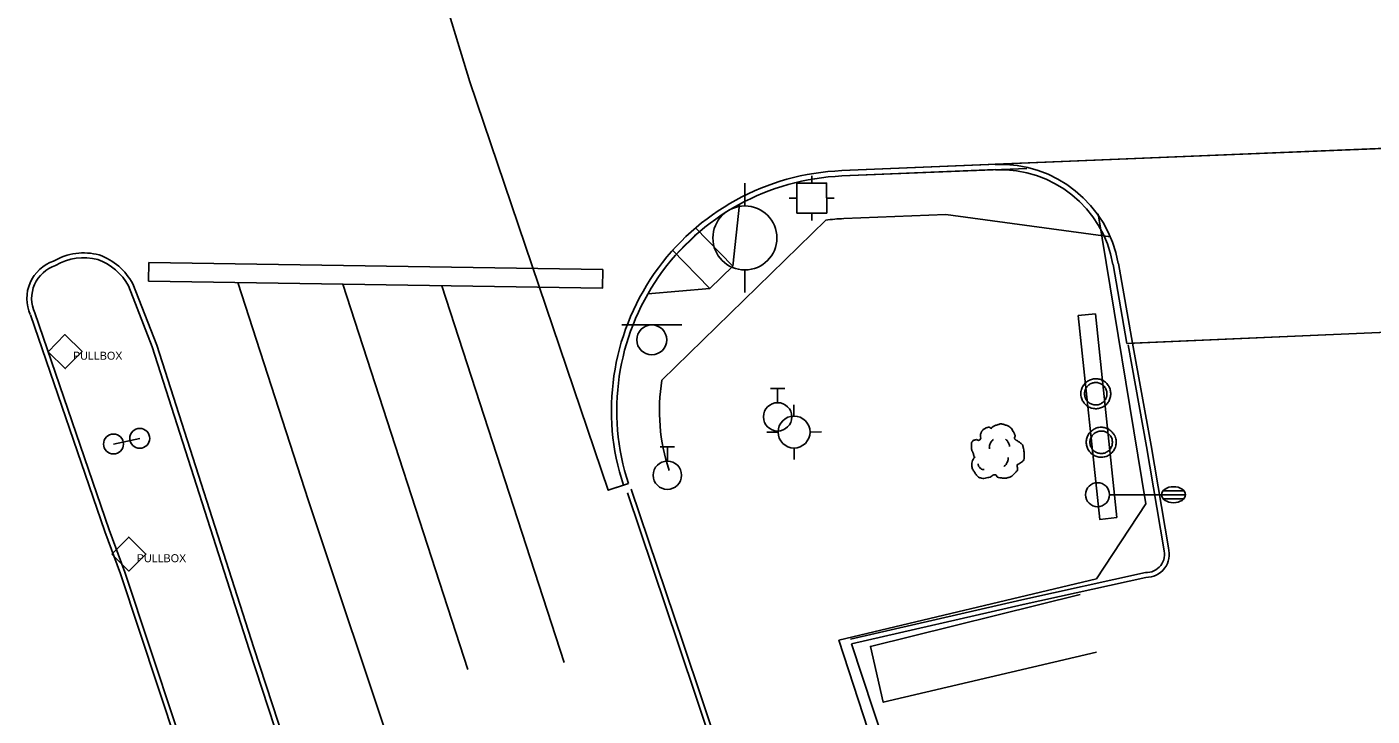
# Model space of a CAD drawing. Extents: x 2145380 to 2157287, y 139568 to 149130.
# Drawn here: x 2147393.3 to 2147561.3, y 142844.8 to 142930.9 of the extents above; entities that cross this region are included whole.
import ezdxf

# ---------------------------------------------------------------- set-up
doc = ezdxf.new("R2010")
doc.units = 0
for name, color, linetype in [('Default', 7, 'Continuous'), ('PR_PREVIOUSLY CONSTRUCTED', 7, 'Continuous'), ('TOPO_Asphalt', 7, 'Continuous'), ('TOPO_Concrete', 7, 'Continuous'), ('TOPO_Curb Back', 7, 'Continuous'), ('TOPO_Guardrail', 7, 'Continuous'), ('TOPO_Light Pole', 7, 'Continuous'), ('TOPO_Misc', 7, 'Continuous'), ('TOPO_Misc Line', 7, 'Continuous'), ('TOPO_Power Pole', 7, 'Continuous'), ('TOPO_Power Pullbox', 7, 'Continuous'), ('TOPO_Sign', 7, 'Continuous'), ('TOPO_Traffic Signal', 7, 'Continuous'), ('TOPO_Tree', 7, 'Continuous'), ('TOPO_Wall Freestanding', 7, 'Continuous'), ('TOPO_Water Fire Hydrant', 7, 'Continuous'), ('TOPO_Water Valve', 7, 'Continuous')]:
    doc.layers.add(name, color=color, linetype=linetype)

# ---------------------------------------------------------------- blocks, each defined once
blk = doc.blocks.new('POST')
at = {"layer": 'TOPO_Misc'}
for start, end in [(90, 180), (180, 270), (360, 90), (270, 0)]:
    blk.add_arc((-0.01, 0.03), 3.16, start, end, dxfattribs=at)
blk = doc.blocks.new('FIRHYD')
at = {"layer": 'TOPO_Water Fire Hydrant'}
for p, q in [((-0.02, 10.16), (-0.03, 17.34)), ((10.16, 0.02), (17.34, 0.03)), ((-10.16, -0.02), (-17.34, -0.03)), ((0.02, -10.16), (0.03, -17.34))]:
    blk.add_line(p, q, dxfattribs=at)
blk.add_circle((0, 0), 10.16, dxfattribs=at)
blk = doc.blocks.new('LP')
at = {"layer": 'TOPO_Light Pole'}
blk.add_line((3.81, 0), (20.32, 0), dxfattribs=at)
for points in [[(20.32, 0), (27.94, 0)], [(20.32, 0), (23.5, 0)], [(20.83, 1.27), (27.43, 1.27)], [(20.83, 1.27), (23.5, 1.27)], [(23.71, 1.27), (27.43, 1.27)], [(23.71, 0), (27.94, 0)], [(20.83, -1.27), (27.43, -1.27)], [(20.83, -1.27), (23.5, -1.27)], [(23.71, -1.27), (27.43, -1.27)]]:
    blk.add_lwpolyline(points, dxfattribs=at)
blk.add_circle((0, 0), 3.81, dxfattribs=at)
blk.add_ellipse((24.13, 0), major_axis=(3.81, 0), ratio=0.666667, dxfattribs=at)
blk = doc.blocks.new('TRFSIG')
at = {"layer": 'TOPO_Traffic Signal'}
for p, q in [((0.04, 4.66), (0.04, 7.04)), ((-4.7, -0.09), (-7.08, -0.09)), ((4.79, -0.09), (7.17, -0.09)), ((0.04, -4.83), (0.04, -7.22))]:
    blk.add_line(p, q, dxfattribs=at)
blk.add_lwpolyline([(-4.7, -4.85), (4.81, -4.83), (4.79, 4.67), (-4.72, 4.66), (-4.7, -4.85)], dxfattribs=at)
blk = doc.blocks.new('TREE')
at = {"layer": 'TOPO_Tree'}
for points in [[(-14.07, -0.4), (-14.17, 0.5), (-14.37, 1.38), (-14.6, 2.25), (-14.84, 3.17), (-15.47, 3.96), (-15.66, 4.9), (-15.8, 5.59), (-15.71, 6.31), (-15.66, 7.01), (-15.6, 7.91), (-15.72, 8.8), (-15.13, 9.66), (-14.62, 10.42), (-13.76, 10.49), (-13.02, 10.72), (-12.18, 10.98), (-11.06, 10), (-10.37, 10.72), (-9.4, 11.74), (-10.29, 13.28), (-9.84, 14.42), (-9.56, 15.15), (-9.32, 15.89), (-8.78, 16.54), (-8.18, 17.26), (-7.5, 17.68), (-6.67, 18.13), (-6.14, 18.41), (-5.61, 18.61), (-5.08, 18.66), (-4.55, 18.71), (-4.02, 18.54), (-3.49, 18.13)], [(-3.49, 17.6), (-3.07, 18.27), (-2.58, 18.8), (-1.9, 19.19), (-1.05, 19.68), (-0.19, 19.96), (0.74, 20.24), (1.62, 20.51), (2.51, 20.82), (3.39, 20.77), (4.1, 20.73), (4.8, 20.47), (5.51, 20.24), (6.43, 19.95), (7.32, 19.73), (8.15, 19.19), (9.36, 18.4), (10.02, 17.21), (10.8, 16.01), (11.24, 15.33), (11.58, 14.62), (11.86, 13.89), (12.17, 13.08), (11.37, 12.02), (11.86, 11.25), (12, 11.03), (12.18, 10.86), (12.39, 10.72), (12.91, 10.35), (13.45, 10.02), (13.97, 9.66), (14.7, 9.16), (15.41, 8.68), (16.09, 8.07), (16.7, 7.53), (16.93, 6.73), (17.15, 5.95), (17.59, 4.38), (17.71, 2.77), (17.68, 1.19), (17.65, -0.25), (17.83, -2.22), (16.62, -3.04), (15.47, -3.83), (14.31, -4.58), (13.16, -5.35)], [(-4.21, 5.09), (-4.46, 6.09), (-4.3, 7.21), (-3.84, 8.21), (-3.33, 9.34), (-2.71, 10.27), (-1.64, 10.97)], [(5.89, 11.15), (6.5, 10.68), (6.96, 10.17), (7.36, 9.5), (7.93, 8.56), (8.31, 7.6), (8.46, 6.56)], [(13.16, -5.34), (13.25, -5.81), (13.36, -6.28), (13.45, -6.75), (13.76, -8.52), (12.24, -10.03), (10.8, -11.51), (9.98, -12.34), (9.13, -12.77), (8.15, -13.1), (5.97, -13.83), (3.32, -13.56), (1.27, -13.1), (0.49, -12.92), (-0.06, -11.44), (-0.84, -11.51), (-2.04, -11.61), (-3.28, -12.78), (-4.55, -13.1), (-6.06, -13.47), (-7.77, -14.03), (-9.31, -13.62), (-11.36, -13.09), (-12.84, -11.41), (-14.07, -9.39), (-15.32, -7.35), (-15.61, -5.13), (-15.13, -3.04), (-14.87, -1.89), (-13.91, -0.75), (-13.54, 0.13)], [(-11.38, -4.46), (-11.47, -5.41), (-11.03, -6.32), (-10.09, -7.22), (-9.3, -7.97), (-8.49, -8.26), (-7.7, -8.14)], [(4.79, -6.29), (5.71, -5.66), (6.3, -4.92), (6.81, -3.91), (7.36, -2.81), (7.63, -1.7), (7.54, -0.6)]]:
    blk.add_open_spline(points, degree=3, dxfattribs=at)
blk = doc.blocks.new('POWPOL')
at = {"layer": 'TOPO_Power Pole'}
for p, q in [((0, 10.16), (0, 17.34)), ((0, -10.16), (0, -17.34))]:
    blk.add_line(p, q, dxfattribs=at)
blk.add_circle((0, 0), 10.16, dxfattribs=at)
blk = doc.blocks.new('pulbox')
at = {"layer": 'Default'}
blk.add_lwpolyline([(-5.38, -0.01), (-0.02, 5.42), (5.4, 0.06), (0.05, -5.36), (-5.38, -0.01)], dxfattribs=at)
blk.add_text('PULLBOX', height=2.54, dxfattribs=at).set_placement((2.54, -2.54))
blk = doc.blocks.new('WATVAL')
at = {"layer": 'Default'}
for p, q in [((-2.25, 9), (2.25, 9)), ((0, 4.5), (0, 9))]:
    blk.add_line(p, q, dxfattribs=at)
blk.add_circle((0, 0), 4.5, dxfattribs=at)

msp = doc.modelspace()

# ---------------------------------------------------------------- linework, layer by layer
at = {"layer": 'PR_PREVIOUSLY CONSTRUCTED'}
for p, q in [((2148111.41, 142938.19), (2147495.09, 142912.98)), ((2147514.28, 142913.1), (2147495.11, 142912.31)), ((2147481.48, 142901.04), (2147482.31, 142908.78)), ((2147508.1, 142907.51), (2147495.33, 142906.98)), ((2147528.65, 142904.68), (2147508.1, 142907.51)), ((2147472.61, 142886.78), (2147493.08, 142906.79)), ((2147474.42, 142902.53), (2147477.29, 142905.33)), ((2147476.77, 142905.85), (2147481.48, 142901.04)), ((2147473.91, 142903.06), (2147478.62, 142898.24)), ((2147478.62, 142898.24), (2147481.48, 142901.04)), ((2147528.98, 142901.26), (2147530.72, 142891.36)), ((2147529.64, 142901.38), (2147531.39, 142891.39)), ((2147470.86, 142897.59), (2147478.62, 142898.24)), ((2147530.72, 142891.36), (2147677.06, 142897.74))]:
    msp.add_line(p, q, dxfattribs=at)
msp.add_lwpolyline([(2147468.44, 142873.85), (2147465.91, 142873.02), (2147448.61, 142924.09), (2147441.56, 142947.18)], dxfattribs=at)
for centre, radius, start, end in [((2147514.86, 142898.77), 15, 9.9849, 92.3423), ((2147496.31, 142883), 30, 92.3423, 198.1765), ((2147496.31, 142883), 29.33, 92.3423, 198.1765), ((2147514.86, 142898.77), 14.33, 9.9849, 92.3423), ((2147496.31, 142883), 24, 92.3423, 97.7373), ((2147496.31, 142883), 24, 170.9577, 198.1765)]:
    msp.add_arc(centre, radius, start, end, dxfattribs=at)
at = {"layer": 'TOPO_Asphalt'}
msp.add_lwpolyline([(2147496.3, 142853.83), (2147508.5, 142816.84), (2147524.71, 142767.27)], dxfattribs=at)
at = {"layer": 'TOPO_Concrete'}
for points in [[(2147573.06, 142916.17), (2147514.25, 142913.76)], [(2147529.64, 142901.38), (2147531.39, 142891.39), (2147570.03, 142893.08)]]:
    msp.add_lwpolyline(points, dxfattribs=at)
msp.add_arc((2147514.86, 142898.77), 15, 9.9849, 92.3423, dxfattribs=at)
at = {"layer": 'TOPO_Curb Back'}
for points in [[(2147467.81, 142873.65), (2147465.91, 142873.02), (2147448.61, 142924.09), (2147441.56, 142947.18), (2147436.88, 142961.43), (2147438.78, 142962.06), (2147443.46, 142947.8)], [(2148111.41, 142938.19), (2147495.09, 142912.98)], [(2147518.22, 142913.25), (2147495.11, 142912.31)], [(2147405.97, 142898.56), (2147408.92, 142890.94), (2147421.05, 142853.12), (2147438.54, 142799.71), (2147447.62, 142773.28)], [(2147406.51, 142898.82), (2147409.49, 142891.14), (2147421.62, 142853.31), (2147439.11, 142799.9), (2147448.19, 142773.47)], [(2147460.18, 142697.55), (2147440.86, 142756.97), (2147424.41, 142805.81), (2147405.51, 142862.78), (2147403.56, 142868.07), (2147394.27, 142895.2)], [(2147459.61, 142697.37), (2147440.29, 142756.78), (2147423.84, 142805.62), (2147404.95, 142862.58), (2147403, 142867.87), (2147393.71, 142894.97)], [(2147530.87, 142891.18), (2147533.14, 142878.51), (2147535.31, 142865.7)], [(2147531.43, 142891.42), (2147533.73, 142878.61), (2147535.89, 142865.84)], [(2147501.98, 142771.3), (2147490.97, 142805.16), (2147474.68, 142853.73), (2147468.3, 142872.71)], [(2147502.56, 142771.44), (2147491.54, 142805.34), (2147475.25, 142853.92), (2147468.78, 142873.16)], [(2147533.02, 142862.74), (2147517.6, 142859.34), (2147496.18, 142854.4)], [(2147533.08, 142862.14), (2147517.73, 142858.75), (2147496.31, 142853.81)]]:
    msp.add_lwpolyline(points, dxfattribs=at)
for centre, radius, start, end in [((2147496.31, 142883), 30, 92.3423, 198.1765), ((2147496.31, 142883), 29.33, 92.3423, 198.1765), ((2147400.38, 142895.27), 7.42, 74.9444, 120.5515), ((2147400.38, 142895.27), 6.82, 75.1665, 121.0713), ((2147399.61, 142895.05), 7.87, 28.6108, 69.8923), ((2147398.21, 142896.99), 4.94, 108.9166, 204.1165), ((2147398.21, 142896.99), 4.34, 108.1176, 204.4649), ((2147399.61, 142895.05), 7.27, 28.9113, 69.6834), ((2147533.12, 142865.02), 2.29, 267.4345, 17.2036), ((2147533.12, 142865.02), 2.89, 269.0909, 16.3686)]:
    msp.add_arc(centre, radius, start, end, dxfattribs=at)
at = {"layer": 'TOPO_Guardrail'}
msp.add_lwpolyline([(2147523.83, 142767.24), (2147508.72, 142811.35), (2147494.73, 142854.27), (2147526.91, 142861.94), (2147533.09, 142871.32), (2147527.13, 142907.57)], dxfattribs=at)
at = {"layer": 'TOPO_Misc Line'}
for p, q in [((2147432.75, 142898.78), (2147448.36, 142850.61)), ((2147445.13, 142898.59), (2147460.42, 142851.48))]:
    msp.add_line(p, q, dxfattribs=at)
msp.add_lwpolyline([(2147408.51, 142901.5), (2147465.23, 142900.61), (2147465.19, 142898.27), (2147408.47, 142899.16)], close=True, dxfattribs=at)
msp.add_lwpolyline([(2147419.65, 142898.98), (2147428.48, 142871.71), (2147450.39, 142805.93), (2147461.38, 142772.28)], dxfattribs=at)
at = {"layer": 'TOPO_Power Pole'}
for points in [[(2147524.95, 142885.09), (2147524.95, 142885.22), (2147524.97, 142885.35), (2147524.99, 142885.47), (2147525.03, 142885.6), (2147525.07, 142885.73), (2147525.12, 142885.85), (2147525.18, 142885.97), (2147525.24, 142886.09), (2147525.32, 142886.2), (2147525.4, 142886.3), (2147525.49, 142886.4), (2147525.59, 142886.49), (2147525.69, 142886.57), (2147525.8, 142886.65), (2147525.91, 142886.72), (2147526.03, 142886.78), (2147526.15, 142886.83), (2147526.27, 142886.87), (2147526.4, 142886.91), (2147526.54, 142886.93), (2147526.67, 142886.95), (2147526.8, 142886.95), (2147526.93, 142886.95), (2147527.06, 142886.94), (2147527.19, 142886.92), (2147527.31, 142886.89), (2147527.44, 142886.85), (2147527.56, 142886.8), (2147527.69, 142886.75), (2147527.8, 142886.68), (2147527.91, 142886.61), (2147528.02, 142886.53), (2147528.11, 142886.44), (2147528.21, 142886.35), (2147528.29, 142886.24), (2147528.37, 142886.13), (2147528.44, 142886.02), (2147528.51, 142885.91), (2147528.56, 142885.78), (2147528.6, 142885.66), (2147528.64, 142885.53), (2147528.67, 142885.4), (2147528.68, 142885.27), (2147528.69, 142885.14), (2147528.69, 142885.01), (2147528.68, 142884.88), (2147528.66, 142884.75), (2147528.63, 142884.62), (2147528.59, 142884.49), (2147528.55, 142884.37), (2147528.49, 142884.25), (2147528.44, 142884.13), (2147528.36, 142884.02), (2147528.28, 142883.91), (2147528.19, 142883.81), (2147528.1, 142883.72), (2147528, 142883.64), (2147527.89, 142883.55), (2147527.78, 142883.48), (2147527.67, 142883.42), (2147527.55, 142883.36), (2147527.42, 142883.31), (2147527.29, 142883.28), (2147527.17, 142883.25), (2147527.04, 142883.23), (2147526.9, 142883.22), (2147526.78, 142883.22), (2147526.65, 142883.23), (2147526.52, 142883.24), (2147526.38, 142883.27), (2147526.26, 142883.3), (2147526.14, 142883.35), (2147526.01, 142883.4), (2147525.89, 142883.47), (2147525.78, 142883.53), (2147525.67, 142883.61), (2147525.57, 142883.7), (2147525.48, 142883.79), (2147525.39, 142883.89), (2147525.31, 142884), (2147525.23, 142884.1), (2147525.17, 142884.21), (2147525.11, 142884.34), (2147525.06, 142884.46), (2147525.02, 142884.59), (2147524.99, 142884.71), (2147524.97, 142884.85), (2147524.95, 142884.98), (2147524.95, 142885.09)], [(2147525.42, 142885.09), (2147525.42, 142885.2), (2147525.44, 142885.31), (2147525.46, 142885.42), (2147525.5, 142885.53), (2147525.54, 142885.64), (2147525.59, 142885.75), (2147525.64, 142885.84), (2147525.71, 142885.94), (2147525.78, 142886.02), (2147525.86, 142886.1), (2147525.95, 142886.19), (2147526.05, 142886.25), (2147526.14, 142886.31), (2147526.24, 142886.36), (2147526.35, 142886.4), (2147526.46, 142886.44), (2147526.57, 142886.46), (2147526.68, 142886.49), (2147526.8, 142886.49), (2147526.91, 142886.49), (2147527.02, 142886.48), (2147527.14, 142886.45), (2147527.25, 142886.42), (2147527.35, 142886.38), (2147527.46, 142886.34), (2147527.55, 142886.28), (2147527.65, 142886.21), (2147527.74, 142886.14), (2147527.83, 142886.07), (2147527.9, 142885.98), (2147527.97, 142885.88), (2147528.03, 142885.79), (2147528.09, 142885.69), (2147528.14, 142885.58), (2147528.17, 142885.47), (2147528.2, 142885.36), (2147528.21, 142885.25), (2147528.22, 142885.14), (2147528.22, 142885.03), (2147528.21, 142884.92), (2147528.19, 142884.8), (2147528.17, 142884.69), (2147528.13, 142884.58), (2147528.08, 142884.48), (2147528.03, 142884.38), (2147527.97, 142884.28), (2147527.9, 142884.19), (2147527.82, 142884.1), (2147527.74, 142884.02), (2147527.64, 142883.95), (2147527.55, 142883.89), (2147527.45, 142883.83), (2147527.34, 142883.78), (2147527.24, 142883.75), (2147527.12, 142883.72), (2147527.01, 142883.7), (2147526.89, 142883.69), (2147526.79, 142883.69), (2147526.68, 142883.7), (2147526.57, 142883.71), (2147526.45, 142883.73), (2147526.34, 142883.77), (2147526.24, 142883.81), (2147526.14, 142883.86), (2147526.04, 142883.93), (2147525.94, 142884), (2147525.86, 142884.07), (2147525.78, 142884.15), (2147525.7, 142884.24), (2147525.64, 142884.34), (2147525.59, 142884.43), (2147525.54, 142884.54), (2147525.49, 142884.65), (2147525.46, 142884.76), (2147525.44, 142884.87), (2147525.42, 142884.98), (2147525.42, 142885.09)], [(2147525.63, 142879.02), (2147525.63, 142879.16), (2147525.65, 142879.29), (2147525.67, 142879.41), (2147525.71, 142879.54), (2147525.75, 142879.67), (2147525.8, 142879.79), (2147525.86, 142879.91), (2147525.92, 142880.03), (2147526, 142880.14), (2147526.08, 142880.24), (2147526.17, 142880.34), (2147526.27, 142880.43), (2147526.37, 142880.51), (2147526.48, 142880.59), (2147526.59, 142880.66), (2147526.71, 142880.72), (2147526.83, 142880.77), (2147526.95, 142880.81), (2147527.08, 142880.85), (2147527.22, 142880.87), (2147527.35, 142880.89), (2147527.48, 142880.89), (2147527.61, 142880.89), (2147527.74, 142880.88), (2147527.87, 142880.86), (2147527.99, 142880.83), (2147528.12, 142880.79), (2147528.24, 142880.74), (2147528.37, 142880.69), (2147528.48, 142880.62), (2147528.59, 142880.55), (2147528.7, 142880.47), (2147528.79, 142880.38), (2147528.89, 142880.28), (2147528.97, 142880.18), (2147529.05, 142880.07), (2147529.12, 142879.96), (2147529.19, 142879.85), (2147529.24, 142879.72), (2147529.28, 142879.6), (2147529.32, 142879.47), (2147529.35, 142879.34), (2147529.36, 142879.21), (2147529.37, 142879.07), (2147529.37, 142878.95), (2147529.36, 142878.82), (2147529.34, 142878.69), (2147529.31, 142878.56), (2147529.27, 142878.43), (2147529.23, 142878.31), (2147529.17, 142878.19), (2147529.12, 142878.07), (2147529.04, 142877.96), (2147528.96, 142877.85), (2147528.87, 142877.75), (2147528.78, 142877.66), (2147528.68, 142877.57), (2147528.57, 142877.49), (2147528.46, 142877.42), (2147528.35, 142877.36), (2147528.23, 142877.3), (2147528.1, 142877.25), (2147527.97, 142877.22), (2147527.85, 142877.19), (2147527.72, 142877.17), (2147527.58, 142877.16), (2147527.46, 142877.16), (2147527.33, 142877.17), (2147527.2, 142877.18), (2147527.06, 142877.21), (2147526.94, 142877.24), (2147526.82, 142877.29), (2147526.69, 142877.34), (2147526.57, 142877.41), (2147526.46, 142877.47), (2147526.35, 142877.55), (2147526.25, 142877.63), (2147526.16, 142877.73), (2147526.07, 142877.82), (2147525.99, 142877.93), (2147525.91, 142878.04), (2147525.85, 142878.15), (2147525.79, 142878.28), (2147525.74, 142878.4), (2147525.7, 142878.53), (2147525.67, 142878.65), (2147525.65, 142878.78), (2147525.63, 142878.92), (2147525.63, 142879.02)], [(2147526.1, 142879.02), (2147526.1, 142879.13), (2147526.12, 142879.25), (2147526.14, 142879.36), (2147526.18, 142879.47), (2147526.22, 142879.58), (2147526.27, 142879.68), (2147526.32, 142879.78), (2147526.39, 142879.87), (2147526.46, 142879.96), (2147526.54, 142880.04), (2147526.63, 142880.12), (2147526.73, 142880.19), (2147526.82, 142880.25), (2147526.92, 142880.3), (2147527.03, 142880.34), (2147527.14, 142880.38), (2147527.25, 142880.4), (2147527.36, 142880.42), (2147527.48, 142880.42), (2147527.59, 142880.42), (2147527.7, 142880.42), (2147527.82, 142880.39), (2147527.93, 142880.36), (2147528.03, 142880.32), (2147528.14, 142880.28), (2147528.23, 142880.22), (2147528.33, 142880.15), (2147528.42, 142880.08), (2147528.51, 142880.01), (2147528.58, 142879.92), (2147528.65, 142879.82), (2147528.71, 142879.73), (2147528.77, 142879.62), (2147528.82, 142879.52), (2147528.85, 142879.41), (2147528.88, 142879.3), (2147528.89, 142879.19), (2147528.9, 142879.07), (2147528.9, 142878.97), (2147528.89, 142878.86), (2147528.87, 142878.74), (2147528.85, 142878.63), (2147528.81, 142878.52), (2147528.76, 142878.42), (2147528.71, 142878.32), (2147528.65, 142878.22), (2147528.58, 142878.12), (2147528.5, 142878.04), (2147528.42, 142877.96), (2147528.32, 142877.89), (2147528.23, 142877.83), (2147528.13, 142877.77), (2147528.02, 142877.72), (2147527.92, 142877.68), (2147527.8, 142877.66), (2147527.69, 142877.63), (2147527.57, 142877.62), (2147527.47, 142877.62), (2147527.36, 142877.63), (2147527.25, 142877.65), (2147527.13, 142877.67), (2147527.02, 142877.71), (2147526.92, 142877.75), (2147526.82, 142877.8), (2147526.72, 142877.87), (2147526.62, 142877.93), (2147526.54, 142878.01), (2147526.46, 142878.09), (2147526.38, 142878.18), (2147526.32, 142878.28), (2147526.27, 142878.37), (2147526.22, 142878.47), (2147526.17, 142878.58), (2147526.14, 142878.7), (2147526.12, 142878.81), (2147526.1, 142878.92), (2147526.1, 142879.02)]]:
    msp.add_lwpolyline(points, dxfattribs=at)
at = {"layer": 'TOPO_Sign'}
for points in [[(2147467.6, 142893.69), (2147475.09, 142893.7)], [(2147471.35, 142893.69), (2147471.35, 142893.69)], [(2147469.48, 142891.82), (2147469.48, 142891.82)], [(2147473.22, 142891.82), (2147473.22, 142891.82)], [(2147471.35, 142889.96), (2147471.35, 142889.96)], [(2147407.38, 142879.5), (2147404.1, 142878.79)]]:
    msp.add_lwpolyline(points, dxfattribs=at)
msp.add_lwpolyline([(2147529.46, 142869.6), (2147526.77, 142895.07), (2147524.63, 142894.85), (2147527.31, 142869.37)], close=True, dxfattribs=at)
for start, end in [(90, 180), (360, 90), (180, 270), (270, 0)]:
    msp.add_arc((2147471.35, 142891.82), 1.87, start, end, dxfattribs=at)
at = {"layer": 'TOPO_Wall Freestanding'}
msp.add_lwpolyline([(2147526.93, 142852.77), (2147500.26, 142846.52), (2147498.66, 142853.51), (2147524.86, 142859.99)], dxfattribs=at)

# ---------------------------------------------------------------- block references
at = {"layer": 'TOPO_Light Pole', "xscale": 0.39370000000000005, "yscale": 0.3937000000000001}
msp.add_blockref('LP', (2147527.04, 142872.47), dxfattribs=at)
at = {"layer": 'TOPO_Misc', "xscale": 0.39370000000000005, "yscale": 0.3937000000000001}
for p in [(2147407.38, 142879.5), (2147404.1, 142878.79)]:
    msp.add_blockref('POST', p, dxfattribs=at)
at = {"layer": 'TOPO_Power Pole', "xscale": 0.39370000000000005, "yscale": 0.3937000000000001}
msp.add_blockref('POWPOL', (2147482.98, 142904.56), dxfattribs=at)
at = {"layer": 'TOPO_Power Pullbox', "xscale": 0.39370000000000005, "yscale": 0.3937000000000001}
for p in [(2147398.04, 142890.34), (2147406.01, 142865.03)]:
    msp.add_blockref('pulbox', p, dxfattribs=at)
at = {"layer": 'TOPO_Traffic Signal', "xscale": 0.39370000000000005, "yscale": 0.3937000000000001}
msp.add_blockref('TRFSIG', (2147491.31, 142909.57), dxfattribs=at)
at = {"layer": 'TOPO_Tree', "xscale": 0.19685000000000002, "yscale": 0.19685000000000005}
msp.add_blockref('TREE', (2147514.38, 142877.22), dxfattribs=at)
at = {"layer": 'TOPO_Water Fire Hydrant', "xscale": 0.19685000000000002, "yscale": 0.19685000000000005}
msp.add_blockref('FIRHYD', (2147489.12, 142880.3), dxfattribs=at)
at = {"layer": 'TOPO_Water Valve', "xscale": 0.39370000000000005, "yscale": 0.3937000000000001}
for p in [(2147487.07, 142882.2), (2147473.3, 142874.9)]:
    msp.add_blockref('WATVAL', p, dxfattribs=at)

doc.saveas('drawing.dxf')
